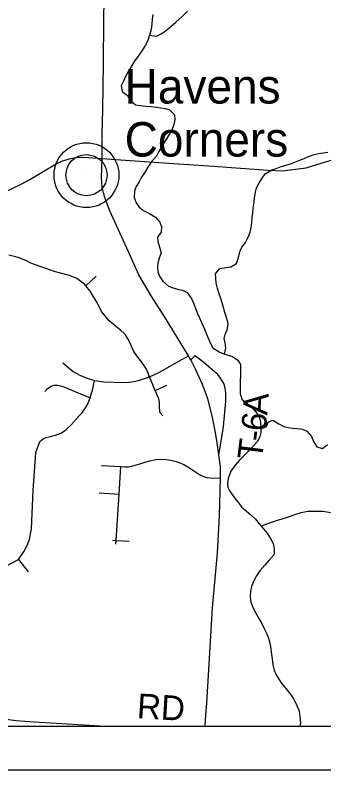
# Model space of a CAD drawing. Extents: x 208586767.6 to 208586821.4, y -134301046.9 to -134301022.9.
# Drawn here: x 208586783.069 to 208586783.778, y -134301030.941 to -134301029.209 of the extents above; entities that cross this region are included whole.
import ezdxf

# ---------------------------------------------------------------- set-up
doc = ezdxf.new("R2010")
doc.units = 0
for name, color, linetype in [('GM_X_Corporation', 7, 'Continuous'), ('GM_X_County_Road', 7, 'Continuous'), ('GM_X_County_Road_Text', 7, 'Continuous'), ('GM_X_Minor_River', 7, 'Continuous'), ('GM_X_Township_Road', 7, 'Continuous'), ('GM_X_Township_Road_Text', 7, 'Continuous'), ('GM_X_Unincorporated', 7, 'Continuous'), ('GM_X_Unincorporated_Location', 7, 'Continuous'), ('GM_X_Unincorporated_Text', 7, 'Continuous'), ('SH_Data', 7, 'Continuous')]:
    doc.layers.add(name, color=color, linetype=linetype)

msp = doc.modelspace()

# ---------------------------------------------------------------- linework, layer by layer
at = {"layer": 'GM_X_Corporation'}
msp.add_lwpolyline([(208586780.4561, -134301030.8407), (208586784.8283, -134301030.8407), (208586784.8283, -134301027.3051), (208586784.2616, -134301027.2694), (208586783.9036, -134301027.2474), (208586783.5221, -134301027.2233), (208586782.8221, -134301027.178), (208586782.72, -134301027.1729), (208586782.648, -134301027.1691), (208586782.6378, -134301027.1684), (208586782.6086, -134301027.1669), (208586782.1685, -134301027.1422), (208586781.98, -134301027.1295), (208586781.8736, -134301027.1231), (208586781.8549, -134301027.122), (208586781.8329, -134301027.1207), (208586781.7344, -134301027.1148), (208586781.7056, -134301027.1139), (208586781.6677, -134301027.1118), (208586781.2713, -134301027.0897)], dxfattribs=at)
at = {"layer": 'GM_X_County_Road'}
msp.add_line((208586783.5052, -134301030.8407), (208586783.5069, -134301030.8145), dxfattribs=at)
for points in [[(208586783.5069, -134301030.8145), (208586783.5087, -134301030.7879), (208586783.5221, -134301030.5685), (208586783.5332, -134301030.4425), (208586783.5378, -134301030.3574), (208586783.54, -134301030.2712), (208586783.5402, -134301030.2449), (208586783.5364, -134301030.2175), (208586783.5328, -134301030.1905), (208586783.5292, -134301030.1664), (208586783.5215, -134301030.1283), (208586783.5112, -134301030.089), (208586783.499, -134301030.0567), (208586783.4836, -134301030.0228), (208586783.4721, -134301029.9994), (208586783.4671, -134301029.9904), (208586783.4396, -134301029.9454), (208586783.4165, -134301029.908), (208586783.4001, -134301029.8827), (208586783.3809, -134301029.8528), (208586783.3524, -134301029.8046), (208586783.3291, -134301029.752), (208586783.2855, -134301029.656), (208586783.2744, -134301029.6274), (208586783.2719, -134301029.6168), (208586783.2688, -134301029.6034), (208586783.267, -134301029.5819), (208586783.2684, -134301029.5377), (208586783.2689, -134301029.4834), (208586783.2697, -134301029.4243), (208586783.2713, -134301029.3217), (208586783.2724, -134301029.22), (208586783.2744, -134301029.0773)], [(208586783.2684, -134301029.5377), (208586783.3875, -134301029.5464), (208586783.5253, -134301029.5557), (208586783.5863, -134301029.5603), (208586783.6494, -134301029.5646), (208586783.6822, -134301029.5661), (208586783.7371, -134301029.5592), (208586783.7717, -134301029.5486), (208586783.7999, -134301029.5404), (208586783.842, -134301029.5277), (208586783.8725, -134301029.5192), (208586783.899, -134301029.5131), (208586783.925, -134301029.5105), (208586783.9583, -134301029.512), (208586783.9759, -134301029.5131), (208586784.0981, -134301029.5214), (208586784.1958, -134301029.5279), (208586784.261, -134301029.5322), (208586784.346, -134301029.5381), (208586784.4606, -134301029.5458), (208586784.5592, -134301029.5524), (208586784.6058, -134301029.5557), (208586784.7129, -134301029.5625), (208586784.8283, -134301029.5704)], [(208586783.023, -134301029.6248), (208586783.0824, -134301029.5965), (208586783.1021, -134301029.5862), (208586783.1349, -134301029.5666), (208586783.1631, -134301029.5502), (208586783.1757, -134301029.544), (208586783.1925, -134301029.5383), (208586783.2078, -134301029.5356), (208586783.2262, -134301029.5351), (208586783.2684, -134301029.5377)], [(208586782.2048, -134301030.7329), (208586782.2147, -134301030.7337), (208586782.3578, -134301030.7436), (208586782.5255, -134301030.7558), (208586782.5589, -134301030.7583), (208586782.6402, -134301030.764), (208586782.7334, -134301030.7706), (208586782.8938, -134301030.7814), (208586782.9255, -134301030.7836), (208586782.9533, -134301030.7886), (208586782.9798, -134301030.7977), (208586783.0144, -134301030.8131), (208586783.0276, -134301030.8176), (208586783.0436, -134301030.8235), (208586783.0702, -134301030.8273), (208586783.1118, -134301030.8302), (208586783.1629, -134301030.8336), (208586783.2387, -134301030.8384), (208586783.2763, -134301030.8407)]]:
    msp.add_lwpolyline(points, dxfattribs=at)
at = {"layer": 'GM_X_Minor_River'}
for points in [[(208586783.3776, -134301029.2551), (208586783.3932, -134301029.257), (208586783.4039, -134301029.2514), (208586783.4134, -134301029.2454), (208586783.4264, -134301029.2348), (208586783.4378, -134301029.225), (208586783.4512, -134301029.2129), (208586783.4642, -134301029.1997)], [(208586783.3852, -134301029.2076), (208586783.3836, -134301029.2178), (208586783.3828, -134301029.2285), (208586783.3812, -134301029.2414), (208586783.3784, -134301029.2527), (208586783.3742, -134301029.2648), (208586783.368, -134301029.2777), (208586783.3596, -134301029.2906), (208586783.3512, -134301029.3027), (208586783.3431, -134301029.3147), (208586783.3358, -134301029.3261), (208586783.3278, -134301029.3397), (208586783.3224, -134301029.3495), (208586783.3174, -134301029.3605), (208586783.3124, -134301029.3711), (208586783.3146, -134301029.384)], [(208586783.3146, -134301029.384), (208586783.3271, -134301029.3932), (208586783.3334, -134301029.405), (208586783.3451, -134301029.4149), (208586783.3554, -134301029.4158), (208586783.369, -134301029.4174), (208586783.38, -134301029.4182), (208586783.3933, -134301029.4202), (208586783.4032, -134301029.4214), (208586783.413, -134301029.4229), (208586783.4229, -134301029.426), (208586783.4346, -134301029.4379), (208586783.4353, -134301029.4481), (208586783.4329, -134301029.4599), (208586783.4283, -134301029.4724), (208586783.4225, -134301029.4826), (208586783.4164, -134301029.4928), (208586783.4068, -134301029.5075), (208586783.3984, -134301029.5215), (208586783.393, -134301029.5321), (208586783.3827, -134301029.5442), (208586783.3731, -134301029.5574), (208586783.3654, -134301029.5703), (208586783.3589, -134301029.5805), (208586783.3532, -134301029.5911), (208586783.347, -134301029.602), (208586783.3428, -134301029.6119), (208586783.3423, -134301029.6271), (208586783.3468, -134301029.6392), (208586783.3539, -134301029.6491), (208586783.3638, -134301029.6568), (208586783.377, -134301029.6641), (208586783.3914, -134301029.6725), (208586783.4012, -134301029.6836), (208586783.4049, -134301029.6946), (208586783.4037, -134301029.7067), (208586783.396, -134301029.7181), (208586783.3963, -134301029.7283), (208586783.4012, -134301029.7432), (208586783.4038, -134301029.7542), (208586783.3995, -134301029.7667), (208586783.3964, -134301029.778), (208586783.3956, -134301029.7875), (208586783.3963, -134301029.7978), (208586783.4004, -134301029.808), (208586783.4079, -134301029.8195), (208586783.4211, -134301029.8306), (208586783.4313, -134301029.8348), (208586783.4435, -134301029.8383), (208586783.4533, -134301029.8402), (208586783.4639, -134301029.8452), (208586783.4748, -134301029.8605), (208586783.4789, -134301029.8711), (208586783.4827, -134301029.8822), (208586783.4868, -134301029.8917), (208586783.4917, -134301029.9016), (208586783.4969, -134301029.9141), (208586783.5021, -134301029.9255), (208586783.5066, -134301029.937), (208586783.5119, -134301029.9499), (208586783.5171, -134301029.9624), (208586783.5227, -134301029.972), (208586783.5371, -134301029.9815), (208586783.5477, -134301029.9862), (208586783.5579, -134301029.9889), (208586783.5681, -134301029.992), (208586783.5802, -134301030.0008), (208586783.5859, -134301030.0103), (208586783.5866, -134301030.0198), (208586783.5861, -134301030.0319), (208586783.5852, -134301030.0524), (208586783.5852, -134301030.0619), (208586783.5855, -134301030.0771), (208586783.5892, -134301030.09), (208586783.6013, -134301030.0996), (208586783.6156, -134301030.1122), (208586783.6243, -134301030.1229), (208586783.6299, -134301030.1328), (208586783.6325, -134301030.143), (208586783.6332, -134301030.1563), (208586783.6327, -134301030.1666), (208586783.6308, -134301030.176), (208586783.625, -134301030.1874), (208586783.6147, -134301030.1987), (208586783.6051, -134301030.2089), (208586783.5937, -134301030.2202), (208586783.5834, -134301030.2304), (208586783.5738, -134301030.2417), (208586783.5642, -134301030.2549), (208586783.558, -134301030.272), (208586783.5565, -134301030.283), (208586783.5575, -134301030.2928), (208586783.5632, -134301030.3031), (208586783.5703, -134301030.3134), (208586783.5793, -134301030.3252), (208586783.5888, -134301030.3371), (208586783.6107, -134301030.3562), (208586783.6208, -134301030.3657), (208586783.6291, -134301030.376), (208586783.6382, -134301030.3871), (208586783.6472, -134301030.3977)], [(208586783.5497, -134301029.9867), (208586783.5527, -134301029.9733), (208586783.5509, -134301029.9611), (208586783.5487, -134301029.9509), (208586783.5514, -134301029.9414), (208586783.5564, -134301029.9289), (208586783.5576, -134301029.916), (208586783.5535, -134301029.9004), (208586783.5506, -134301029.8909), (208586783.5472, -134301029.8799), (208586783.5442, -134301029.8689), (208586783.5409, -134301029.859), (208586783.5372, -134301029.848), (208586783.5334, -134301029.8362), (208586783.5305, -134301029.8236), (208586783.5294, -134301029.8126), (208586783.5291, -134301029.8028), (208586783.539, -134301029.7899), (208586783.5531, -134301029.7877), (208586783.5637, -134301029.7866), (208586783.5771, -134301029.7788), (208586783.5817, -134301029.7647), (208586783.5848, -134301029.7519), (208586783.5894, -134301029.7409), (208586783.5975, -134301029.7303), (208586783.6044, -134301029.7171), (208586783.6086, -134301029.7065), (208586783.6106, -134301029.6966), (208586783.6122, -134301029.6845), (208586783.6134, -134301029.6731), (208586783.6142, -134301029.6621), (208586783.6154, -134301029.6519), (208586783.6178, -134301029.6378), (208586783.6186, -134301029.628), (208586783.6206, -134301029.6147), (208586783.6229, -134301029.6052), (208586783.6287, -134301029.595), (208586783.636, -134301029.5829), (208586783.6429, -134301029.5731), (208586783.6581, -134301029.5641), (208586783.6684, -134301029.5607), (208586783.6794, -134301029.5562), (208586783.6931, -134301029.5525), (208586783.7053, -134301029.5484), (208586783.7205, -134301029.5425), (208586783.7327, -134301029.5376), (208586783.7426, -134301029.5331), (208586783.7528, -134301029.529), (208586783.7654, -134301029.5264), (208586783.7764, -134301029.525), (208586783.787, -134301029.5231)], [(208586783.6331, -134301030.1582), (208586783.6457, -134301030.1526), (208586783.6499, -134301030.1427), (208586783.6602, -134301030.1379), (208586783.6742, -134301030.1467), (208586783.6856, -134301030.1525), (208586783.6958, -134301030.1548), (208586783.7057, -134301030.1567), (208586783.7167, -134301030.1576), (208586783.7288, -134301030.1592), (208586783.7386, -134301030.1634), (208586783.7492, -134301030.176), (208586783.754, -134301030.187), (208586783.7619, -134301030.1992), (208586783.7748, -134301030.2031), (208586783.7859, -134301030.1937)], [(208586783.633, -134301030.3807), (208586783.6363, -134301030.3798), (208586783.6512, -134301030.3746), (208586783.6607, -134301030.3713), (208586783.6713, -134301030.3675), (208586783.6823, -134301030.3646), (208586783.6919, -134301030.3612), (208586783.7014, -134301030.3582), (208586783.7135, -134301030.3537), (208586783.7257, -134301030.3504), (208586783.742, -134301030.3471), (208586783.7531, -134301030.3468), (208586783.7641, -134301030.3468), (208586783.7762, -134301030.3473), (208586783.7929, -134301030.3501)], [(208586783.6472, -134301030.3977), (208586783.6551, -134301030.4096), (208586783.6615, -134301030.4214), (208586783.6637, -134301030.4331), (208586783.6632, -134301030.4468), (208586783.6521, -134301030.4593), (208586783.6422, -134301030.471), (208586783.6304, -134301030.4842), (208586783.6231, -134301030.4951), (208586783.6158, -134301030.5084), (208586783.6112, -134301030.5201), (208586783.6092, -134301030.5303), (208586783.6084, -134301030.5432), (208586783.6102, -134301030.5561), (208586783.6161, -134301030.5714), (208586783.6214, -134301030.5809), (208586783.6285, -134301030.5934), (208586783.6346, -134301030.603), (208586783.6405, -134301030.6159), (208586783.6465, -134301030.6285), (208586783.6503, -134301030.6387), (208586783.654, -134301030.6532), (208586783.6558, -134301030.6638), (208586783.6572, -134301030.6756), (208586783.6587, -134301030.6858), (208586783.6605, -134301030.6999), (208586783.6639, -134301030.7117), (208586783.6676, -134301030.7212), (208586783.6744, -134301030.7322), (208586783.6819, -134301030.7437), (208586783.6902, -134301030.7536), (208586783.7018, -134301030.7688), (208586783.7094, -134301030.7803), (208586783.7157, -134301030.7928), (208586783.7206, -134301030.8061), (208586783.7228, -134301030.8179), (208586783.7238, -134301030.8327), (208586783.7225, -134301030.8407)]]:
    msp.add_lwpolyline(points, dxfattribs=at)
at = {"layer": 'GM_X_Township_Road'}
for p, q in [((208586783.2312, -134301029.8296), (208586783.2549, -134301029.8077)), ((208586783.3906, -134301030.0701), (208586783.4167, -134301030.0578)), ((208586783.2619, -134301030.3053), (208586783.3073, -134301030.3082)), ((208586783.3, -134301030.4226), (208586783.3005, -134301030.4141)), ((208586783.0763, -134301030.4583), (208586783.0989, -134301030.4862))]:
    msp.add_line(p, q, dxfattribs=at)
for points in [[(208586783.3774, -134301030.0388), (208586783.3701, -134301030.0212), (208586783.3585, -134301030.0041), (208586783.3479, -134301029.9908), (208586783.3416, -134301029.9808), (208586783.3372, -134301029.9719), (208586783.3322, -134301029.9599), (208586783.327, -134301029.9499), (208586783.3225, -134301029.9426), (208586783.3198, -134301029.9399), (208586783.3108, -134301029.9318), (208586783.2847, -134301029.9099), (208586783.268, -134301029.8896), (208586783.2561, -134301029.8677), (208586783.2411, -134301029.8423), (208586783.2312, -134301029.8296), (208586783.2279, -134301029.8265), (208586783.2101, -134301029.8135), (208586783.1932, -134301029.8061), (208586783.1582, -134301029.7967), (208586783.1413, -134301029.7913), (208586783.1046, -134301029.778), (208586783.0936, -134301029.7716), (208586783.0756, -134301029.765), (208586783.0541, -134301029.7594)], [(208586783.1785, -134301030.0067), (208586783.2023, -134301030.0262), (208586783.2176, -134301030.0346), (208586783.232, -134301030.0413), (208586783.2506, -134301030.0472), (208586783.2727, -134301030.0506), (208586783.296, -134301030.0513), (208586783.3253, -134301030.0516), (208586783.3414, -134301030.0497), (208586783.3523, -134301030.0469), (208586783.3774, -134301030.0388), (208586783.399, -134301030.0285), (208586783.4137, -134301030.0205), (208586783.445, -134301030.003), (208586783.4671, -134301029.9904)], [(208586783.5364, -134301030.2175), (208586783.5441, -134301030.1729), (208586783.5469, -134301030.1529), (208586783.5526, -134301030.0956), (208586783.5528, -134301030.0764), (208586783.5512, -134301030.0642), (208586783.5479, -134301030.0541), (208586783.5406, -134301030.0417), (208586783.5339, -134301030.0334), (208586783.5269, -134301030.0273), (208586783.5074, -134301030.0107), (208586783.4952, -134301030.0009), (208586783.4888, -134301029.9957), (208586783.4816, -134301029.9903), (208586783.4801, -134301029.9911), (208586783.479, -134301029.9929), (208586783.4721, -134301029.9994)], [(208586783.049, -134301030.4725), (208586783.0763, -134301030.4583), (208586783.0895, -134301030.4391), (208586783.0974, -134301030.4244), (208586783.1015, -134301030.4114), (208586783.1059, -134301030.3878), (208586783.1098, -134301030.2997), (208586783.1161, -134301030.2123), (208586783.1254, -134301030.1874), (208586783.1331, -134301030.1812), (208586783.1396, -134301030.1777), (208586783.1613, -134301030.1729), (208586783.1735, -134301030.168), (208586783.1822, -134301030.163), (208586783.186, -134301030.16), (208586783.1972, -134301030.1492), (208586783.216, -134301030.1281), (208586783.2223, -134301030.1211), (208586783.2304, -134301030.1102), (208586783.2352, -134301030.102), (208586783.2407, -134301030.0872), (208586783.2471, -134301030.0662), (208586783.2506, -134301030.0472)], [(208586783.408, -134301030.1284), (208586783.4015, -134301030.1213), (208586783.3999, -134301030.1101), (208586783.3999, -134301030.0961), (208586783.3987, -134301030.0892), (208586783.3906, -134301030.0701), (208586783.3774, -134301030.0388)], [(208586783.137, -134301030.0726), (208586783.1427, -134301030.0655), (208586783.1516, -134301030.0602), (208586783.1585, -134301030.0582), (208586783.1651, -134301030.0577), (208586783.1763, -134301030.0602), (208586783.1843, -134301030.0636), (208586783.2044, -134301030.0719), (208586783.2407, -134301030.0872)], [(208586783.2659, -134301030.242), (208586783.3113, -134301030.2449), (208586783.3198, -134301030.2454), (208586783.3293, -134301030.2452), (208586783.3386, -134301030.2432), (208586783.3549, -134301030.2381), (208586783.377, -134301030.2314), (208586783.3921, -134301030.2286), (208586783.4038, -134301030.2279), (208586783.4154, -134301030.2284), (208586783.426, -134301030.2298), (208586783.4388, -134301030.233), (208586783.4448, -134301030.2351), (208586783.4558, -134301030.2399), (208586783.4653, -134301030.2452), (208586783.4781, -134301030.2537), (208586783.492, -134301030.2629), (208586783.5015, -134301030.2678), (208586783.5092, -134301030.27), (208586783.5173, -134301030.2708), (208586783.54, -134301030.2712)], [(208586783.3005, -134301030.4141), (208586783.3073, -134301030.3082), (208586783.3113, -134301030.2449)], [(208586783.292, -134301030.4135), (208586783.3005, -134301030.4141), (208586783.3308, -134301030.416)]]:
    msp.add_lwpolyline(points, dxfattribs=at)
at = {"layer": 'GM_X_Unincorporated'}
for radius in [0.0744, 0.0472]:
    msp.add_circle((208586783.2325, -134301029.576), radius, dxfattribs=at)
at = {"layer": 'GM_X_Unincorporated_Location'}
msp.add_line((208586783.2325, -134301029.576), (208586783.2325, -134301029.576), dxfattribs=at)
at = {"layer": 'SH_Data'}
for p, q in [((208586778.0283, -134301030.8407), (208586784.8283, -134301030.8407)), ((208586777.9283, -134301030.9407), (208586784.9283, -134301030.9407))]:
    msp.add_line(p, q, dxfattribs=at)

# ---------------------------------------------------------------- texts
at = {"layer": 'GM_X_County_Road_Text'}
msp.add_text('RD', height=0.05682, rotation=356.5467, dxfattribs=at).set_placement((208586783.3474, -134301030.8218))
at = {"layer": 'GM_X_Township_Road_Text'}
for s, rotation, p in [('A', 86.0271, (208586783.6478, -134301030.1278)), ('6', 83.2118, (208586783.6434, -134301030.1655)), ('-', 83.0175, (208586783.6405, -134301030.1889)), ('T', 82.9627, (208586783.6353, -134301030.2312))]:
    msp.add_text(s, height=0.0568, rotation=rotation, dxfattribs=at).set_placement(p)
at = {"layer": 'GM_X_Unincorporated_Text'}
for s, p in [('Havens', (208586783.3202, -134301029.4116)), ('Corners', (208586783.3202, -134301029.5333))]:
    msp.add_text(s, height=0.07898, rotation=0, dxfattribs=at).set_placement(p)

doc.saveas('drawing.dxf')
